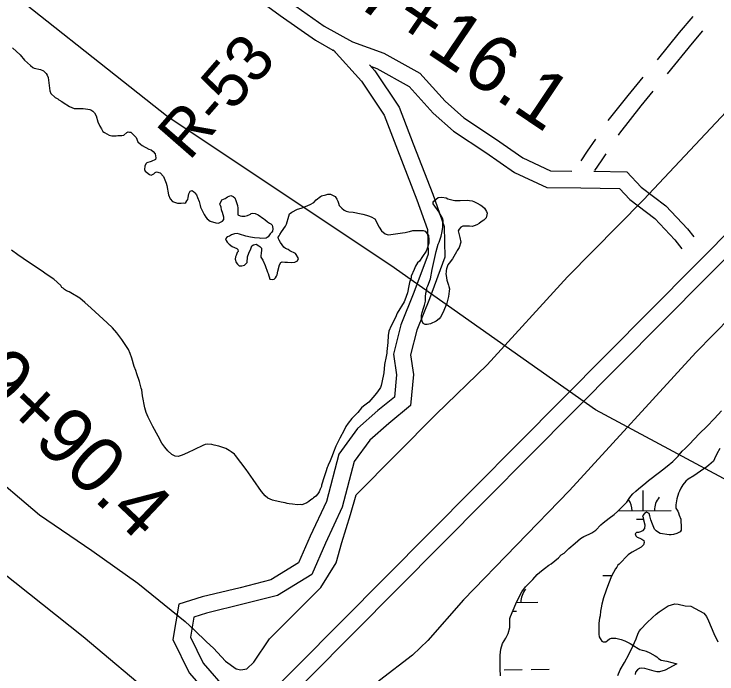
# Model space of a CAD drawing. Extents: x 3146026 to 3183936, y 897894 to 923344.
# Drawn here: x 3174210 to 3175467, y 911149 to 912329 of the extents above; entities that cross this region are included whole.
import ezdxf

# ---------------------------------------------------------------- set-up
doc = ezdxf.new("R2010")
doc.units = 0
for name, color, linetype in [('V-LEVE-TOET', 7, 'Continuous'), ('V-RIVR-RANG-IDEN', 7, 'Continuous'), ('V-ROAD-CNTR', 7, 'Continuous'), ('V-SITE-VEGE', 7, 'Continuous'), ('V-SURV-IDEN', 7, 'Continuous'), ('V-SURV-LINE', 7, 'Continuous'), ('V-TOPO-BNDY', 7, 'Continuous'), ('V-WETL-SWMP', 7, 'Continuous')]:
    doc.layers.add(name, color=color, linetype=linetype)

msp = doc.modelspace()

# ---------------------------------------------------------------- linework, layer by layer
at = {"layer": 'V-LEVE-TOET'}
for points in [[(3172100.1, 913448.3), (3172370.8, 913233.9), (3172398.7, 913212.6), (3172497.8, 913129.1), (3172624.4, 912974.6), (3172787.3, 912807.3), (3172980.7, 912627.4), (3173171.4, 912446.8), (3173377.7, 912260.1), (3173591.1, 912050.9), (3173767.1, 911895.3), (3173843.3, 911824.3), (3173892.6, 911768.4), (3173997.2, 911662.3), (3174154.9, 911518.6), (3174255.5, 911433.9), (3174348.6, 911370.2), (3174431.4, 911311.7), (3174516, 911243.3)], [(3176559, 912918.7), (3176436.3, 912775.6), (3176341.7, 912684.2), (3176241.8, 912571), (3176075.2, 912402.9), (3175880.3, 912204.7), (3175650.4, 911949.6), (3175429.3, 911724.1), (3175203.1, 911477.4), (3175013.4, 911281.9), (3174949.6, 911208.9), (3174922.4, 911183.2), (3174863.1, 911137.7), (3174821.7, 911101.7)], [(3174516, 911243.3), (3174532.2, 911227.5), (3174553.9, 911206.8), (3174566.6, 911195.5), (3174587.9, 911172.2), (3174607, 911158.4), (3174615.1, 911156.6), (3174626.2, 911158.8), (3174638.6, 911170.2), (3174666.6, 911212.4), (3174758.5, 911304.2), (3174785.9, 911348.2), (3174796, 911384.2), (3174811.4, 911434.2), (3174821.7, 911469.5), (3174964.9, 911614.1), (3175056, 911701.9), (3175199.6, 911859.6), (3175335.6, 911997.2), (3175501.9, 912173.9)], [(3174465.1, 911105.1), (3174333.2, 911215.8), (3174187.8, 911331.4)]]:
    msp.add_lwpolyline(points, dxfattribs=at)
at = {"layer": 'V-ROAD-CNTR'}
msp.add_line((3174779.5, 912264.5), (3174779.9, 912264.2), dxfattribs=at)
for points in [[(3174155.7, 912709.2), (3174233.7, 912670.7), (3174298.8, 912628.9), (3174369.4, 912570.8), (3174446, 912498.5), (3174540.9, 912435.8), (3174615.5, 912378.5), (3174685.8, 912326.4), (3174748.6, 912282.2), (3174784.2, 912262.3)], [(3174580.7, 912443.1), (3174633.6, 912402.5), (3174703.3, 912350.7), (3174764.6, 912307.7), (3174815.1, 912279.3), (3174870.9, 912259.2), (3174935.4, 912223.3), (3174980.6, 912173.5), (3175014.1, 912143.9), (3175070.5, 912106.2), (3175119.7, 912072.1), (3175169.2, 912048.9), (3175207.4, 912048.5)], [(3175423.4, 912324.7), (3175399.3, 912296.1), (3175359.9, 912247.5)], [(3175441.2, 912299.4), (3175422.4, 912277), (3175377.8, 912222)], [(3174780.3, 912265.3), (3174831.4, 912209.2), (3174871.4, 912148.6), (3174895.8, 912086.5), (3174930.3, 911996.8), (3174949.2, 911943.8), (3174950.2, 911899.7), (3174924.6, 911831.2), (3174901.2, 911773.6), (3174888.1, 911721.1), (3174894, 911683.9), (3174889.9, 911644.5), (3174860.5, 911620.1), (3174823.8, 911588), (3174790.7, 911542.6), (3174768.5, 911457.7), (3174739.2, 911395.6), (3174718.5, 911348), (3174669, 911317.8), (3174614.2, 911303.6), (3174546, 911287), (3174504.7, 911274.3), (3174493.8, 911210.8), (3174522.8, 911151.6), (3174569.5, 911098.1)], [(3174845.5, 912238.3), (3174855.2, 912227.7), (3174898.2, 912162.5), (3174923.7, 912097.3), (3174958.5, 912007.3), (3174979.1, 911949.3), (3174980.3, 911894.6), (3174952.6, 911820.3), (3174929.8, 911764.3), (3174918.7, 911719.7), (3174924.2, 911684.8), (3174918.5, 911629.3), (3174880, 911597.2), (3174846, 911567.6), (3174818.3, 911529.5), (3174796.8, 911447.5), (3174766.5, 911383.2), (3174742.3, 911327.3), (3174680.8, 911289.9), (3174621.5, 911274.5), (3174554, 911258), (3174531.1, 911251), (3174525, 911215.3), (3174548, 911168.4), (3174591.3, 911118.8)], [(3174849.2, 912235.1), (3174858.5, 912231.8), (3174916.5, 912199.5), (3174959.5, 912152.1), (3174995.8, 912120), (3175053.6, 912081.4), (3175104.7, 912046), (3175162.4, 912018.9), (3175223.6, 912018.4), (3175292.6, 912017.3), (3175310.9, 911997.5), (3175355.5, 911963.6), (3175391.6, 911925.7), (3175404.3, 911909.3)], [(3175334.5, 912216.6), (3175307.3, 912183.8), (3175271.9, 912138.7)], [(3175352.4, 912191.2), (3175330.7, 912164.9), (3175292.6, 912116.5), (3175290.3, 912112.8)], [(3175249.8, 912105.4), (3175235, 912083.8), (3175223.1, 912066.9)], [(3175268.3, 912079.4), (3175259.6, 912066.7), (3175247.6, 912049.7)], [(3175246.4, 912048), (3175305.9, 912047.1), (3175331.2, 912019.8), (3175375.5, 911986), (3175414.4, 911945.3), (3175425.5, 911930.9)]]:
    msp.add_lwpolyline(points, dxfattribs=at)
at = {"layer": 'V-SITE-VEGE'}
for points in [[(3174206.8, 912268.9), (3174220.9, 912256), (3174228.7, 912246.6), (3174238.9, 912236.9), (3174243.2, 912233.4), (3174245.9, 912232.2), (3174257.3, 912229.9), (3174262.4, 912227.5), (3174267, 912222.9), (3174269, 912220.1), (3174271, 912215.5), (3174273.7, 912192), (3174275.3, 912186.9), (3174283.5, 912179.9), (3174288.2, 912177.6), (3174289.8, 912176), (3174294.9, 912172.9), (3174297.6, 912171), (3174309, 912163.9), (3174317.2, 912160.1), (3174333.6, 912160.1), (3174341.4, 912159.3), (3174345.3, 912158.5), (3174347.2, 912157.8), (3174350.8, 912155.8), (3174353.9, 912152.7), (3174356.6, 912147.2), (3174359.8, 912136.7), (3174362.9, 912128.9), (3174366.1, 912124.2), (3174368.8, 912119.1), (3174371.5, 912117.2), (3174379.8, 912112.5), (3174384.4, 912111.3), (3174386.8, 912111.7), (3174392.6, 912111.7), (3174395.4, 912112.1), (3174402.4, 912112.1), (3174405.9, 912112.9), (3174411.4, 912117.2), (3174413.7, 912118.4), (3174416.1, 912118), (3174418.8, 912118), (3174428.2, 912108.7), (3174431, 912100.9), (3174435.6, 912096.6), (3174438.8, 912094.2), (3174450.9, 912087.6), (3174454.8, 912086.5), (3174458.7, 912083.3), (3174461.9, 912079.4), (3174463.4, 912072), (3174462.7, 912069.3), (3174454.8, 912065.4), (3174447.4, 912063), (3174445.5, 912061.4), (3174443.5, 912057.1), (3174442.8, 912051.3), (3174444.3, 912048.5), (3174446.7, 912046.2), (3174451.8, 912042.3), (3174454.9, 912041.1), (3174459.6, 912043.5), (3174462.3, 912045.8)], [(3174462.3, 912045.8), (3174464.6, 912047), (3174470.9, 912045.1), (3174476.8, 912038.8), (3174479.5, 912032.6), (3174481.9, 912026.7), (3174483, 912022.8), (3174485.8, 912006), (3174489, 911998.6), (3174493.3, 911994.3), (3174502.2, 911991.2), (3174505.4, 911991.2), (3174508.5, 911990.8), (3174512.4, 911991.6), (3174515.1, 911991.2), (3174517.1, 911992.4), (3174519, 911995.1), (3174520.6, 911997.9), (3174521.4, 912001), (3174522.5, 912008), (3174524.9, 912012.7), (3174528, 912013.5), (3174531.1, 912011.6), (3174533.1, 912009.6), (3174535.8, 912006.1), (3174537.8, 912001), (3174540.9, 911994), (3174542.5, 911987), (3174543.3, 911984.2), (3174546, 911978), (3174548.8, 911972.9), (3174549.6, 911971), (3174552.7, 911965.9), (3174555.4, 911963.2), (3174560.5, 911958.9), (3174570.7, 911955.8), (3174575.4, 911955.4), (3174580, 911957.4), (3174582.4, 911958.9), (3174585.1, 911961.7), (3174585.1, 911966), (3174582.4, 911974.2), (3174581.6, 911977.3), (3174580.8, 911979.2), (3174580, 911983.9), (3174578.8, 911987), (3174577.7, 911989.4), (3174581.5, 911996.8), (3174587, 911999.6), (3174589, 912000.3), (3174591.3, 912002.3), (3174597.2, 912005), (3174601.5, 912003.1), (3174604.6, 912000.4), (3174606.6, 911995.7), (3174609.3, 911986.7), (3174610.1, 911982.4), (3174610.1, 911977.7), (3174609.7, 911975), (3174610.1, 911970.3), (3174614.4, 911968.4), (3174617.1, 911968), (3174622.6, 911968), (3174627.3, 911969.2), (3174632.4, 911971.1), (3174633.9, 911972.7), (3174636.3, 911973.1), (3174641, 911972.3), (3174646.1, 911970), (3174656.2, 911963), (3174658.2, 911961.8), (3174662.9, 911957.5), (3174666.4, 911955.5), (3174668.7, 911954), (3174671.1, 911951.6), (3174671.9, 911949.3), (3174672.3, 911945.4), (3174671.9, 911941.1), (3174670.7, 911939.1), (3174668, 911936.4), (3174664.1, 911930.9), (3174660.6, 911928.6), (3174651.2, 911927.8), (3174648.9, 911928.6), (3174639.5, 911928.9), (3174632.4, 911930.5), (3174624.2, 911932), (3174612.9, 911935.5), (3174608.6, 911936.7), (3174603.9, 911936.3), (3174598.5, 911934.3), (3174594.9, 911932), (3174591, 911930.8), (3174587.9, 911927.3), (3174589.1, 911924.6), (3174591, 911921.4), (3174594.6, 911917.9), (3174600.1, 911913.6), (3174608.3, 911910.1), (3174609.8, 911908.2), (3174610.6, 911904.7)], [(3174610.6, 911904.7), (3174608.7, 911902.7), (3174607.1, 911897.6), (3174605.9, 911894.9), (3174605.2, 911891), (3174606.7, 911884.7), (3174609.1, 911882), (3174612.2, 911879.3), (3174615, 911878.9), (3174617.3, 911878.9), (3174622, 911880.1), (3174626.7, 911884.8), (3174627.4, 911895.3), (3174629.4, 911901.6), (3174633.3, 911909.4), (3174635.2, 911914.9), (3174637.9, 911916.4), (3174642.6, 911918), (3174647.3, 911914.9), (3174649.3, 911913.3), (3174652, 911910.6), (3174652.4, 911907.5), (3174651.6, 911900.8), (3174650.9, 911897.3), (3174650.9, 911894.6), (3174654.4, 911889.1), (3174659.1, 911879.4), (3174663, 911868), (3174664.2, 911865.3), (3174667.3, 911855.1), (3174671.3, 911854.4), (3174674.8, 911855.2), (3174677.1, 911857.5), (3174679.1, 911860.6), (3174680.2, 911863), (3174681.4, 911869.6), (3174684.5, 911881), (3174686.8, 911884.9), (3174689.2, 911886), (3174693.9, 911885.7), (3174698.5, 911885.7), (3174706.8, 911884.9), (3174711.8, 911885.7), (3174716.5, 911888), (3174718.5, 911892.3), (3174714.5, 911899.4), (3174713, 911900.9), (3174703.2, 911906), (3174700.1, 911908.3), (3174695, 911910.3), (3174692.3, 911912.2), (3174689.1, 911916.5), (3174686.4, 911920.8), (3174683.6, 911924.7), (3174682.5, 911927.1), (3174682.1, 911930.2), (3174684, 911932.9), (3174685.2, 911935.3), (3174688.3, 911940), (3174695.3, 911949.7), (3174696.9, 911953.6), (3174701.1, 911967.7), (3174702.3, 911972), (3174706.6, 911975.2), (3174716.7, 911980.2), (3174723.4, 911982.2), (3174730.8, 911985), (3174739.4, 911988.5), (3174746, 911992.4), (3174750.3, 911997.1), (3174757.7, 912003), (3174759.7, 912004.2), (3174767.5, 912006.1), (3174771, 912007.3), (3174775.7, 912006.9), (3174783.9, 912003), (3174787, 911998.3), (3174789, 911994.8), (3174789.8, 911991.3), (3174791.4, 911987), (3174796.1, 911981.9), (3174800, 911978.8), (3174803.9, 911976.5), (3174808.2, 911975.7), (3174816, 911974.9), (3174830.8, 911971.9), (3174833.6, 911971.1), (3174840.2, 911969.9), (3174843.4, 911968.4), (3174848.4, 911966.4), (3174855.1, 911963.3), (3174857.4, 911959), (3174860.2, 911952.4), (3174862.5, 911948.1), (3174866.8, 911941.8), (3174873.5, 911936), (3174877, 911934.8), (3174879.4, 911934.4), (3174892.2, 911936.4), (3174904.7, 911938), (3174909.4, 911938.8)], [(3174909.4, 911938.8), (3174913.7, 911940), (3174917.2, 911940.4), (3174923.1, 911941.9), (3174926.2, 911941.9), (3174934.8, 911942.3), (3174941.5, 911942.3), (3174945, 911941.2), (3174950.8, 911933), (3174951.6, 911926), (3174951.6, 911923.2), (3174951.3, 911919.3), (3174948.5, 911909.9), (3174946.6, 911905.2), (3174940.4, 911895.5), (3174934.9, 911887.3), (3174931, 911884.1), (3174927.5, 911878.6), (3174925.2, 911872.4), (3174920.1, 911860.3), (3174919.7, 911857.5), (3174917, 911849.3), (3174915.5, 911843.5), (3174913.1, 911831), (3174908.9, 911817.7), (3174907.7, 911814.5), (3174894.8, 911794.2), (3174891.7, 911786.8), (3174883.9, 911771.5), (3174880, 911762.5), (3174878.9, 911754.7), (3174878.1, 911741.8), (3174876.6, 911725.8), (3174876.6, 911722.7), (3174875, 911716.8), (3174872.3, 911702.4), (3174870.8, 911687.5), (3174867.7, 911670.7), (3174866.5, 911664.8), (3174865, 911661.3), (3174859.9, 911653.9), (3174854.8, 911647.6), (3174844.3, 911635.5), (3174834.6, 911628.1), (3174831.1, 911624.9), (3174824.4, 911617.1), (3174821.7, 911613.6), (3174817, 911608.9), (3174813.9, 911606.1), (3174807.3, 911597.9), (3174803, 911591.7), (3174799.9, 911585), (3174792.1, 911570.9), (3174785.1, 911556.9), (3174781.2, 911545.9), (3174778.5, 911539.3), (3174775.3, 911530.7), (3174771.5, 911522.9), (3174770.7, 911520.9), (3174769.9, 911518.6), (3174767.2, 911510.7), (3174764.1, 911501.7), (3174759.8, 911486.9), (3174759.4, 911484.5), (3174757.8, 911481), (3174757.1, 911479.5), (3174755.5, 911475.2), (3174753.2, 911471.3), (3174749.7, 911467), (3174745.4, 911464.2), (3174743.4, 911462.3), (3174740.7, 911460.7), (3174736.8, 911457.9), (3174733.3, 911455.6), (3174729, 911453.6), (3174724.3, 911451.7), (3174721.6, 911452.1), (3174716.9, 911452), (3174707.5, 911452.8), (3174701.6, 911453.6), (3174698.1, 911454.4), (3174694.6, 911455.1), (3174687.2, 911456.3), (3174674.3, 911459.4), (3174671.9, 911459.8), (3174663.7, 911463.7), (3174658.6, 911468), (3174652, 911475.4), (3174637.1, 911496.8), (3174633.2, 911503.1), (3174628.9, 911508.9), (3174625, 911514.8), (3174615.2, 911527.7), (3174605.8, 911540.2), (3174603.8, 911542.1), (3174598.3, 911546.4), (3174594.4, 911548.7), (3174588.2, 911552.6), (3174575.7, 911556.9), (3174567.5, 911558.4), (3174563.5, 911559.6)], [(3174563.5, 911559.6), (3174555.7, 911560.4), (3174551.4, 911559.6), (3174547.5, 911557.6), (3174532.3, 911550.6), (3174520.2, 911544.7), (3174510.1, 911540.8), (3174503.4, 911538.4), (3174497.6, 911538.8), (3174491.7, 911541.9), (3174484.6, 911548.5), (3174479.6, 911554.8), (3174474.1, 911561.8), (3174467.4, 911574.3), (3174458, 911591.5), (3174449.4, 911608.6), (3174445.9, 911616.8), (3174443.5, 911625.4), (3174439.5, 911646.9), (3174438, 911657.1), (3174436.8, 911660.6), (3174434, 911672.3), (3174429.3, 911686), (3174427.4, 911692.2), (3174424.6, 911699.2), (3174420.3, 911713.7), (3174417.5, 911722.3), (3174414.4, 911729.3), (3174402.7, 911747.3), (3174393.6, 911759.3), (3174385.8, 911767.9), (3174376, 911776.9), (3174347.9, 911803.4), (3174336.5, 911813.2), (3174327.1, 911821), (3174311.1, 911830.7), (3174308.3, 911832.3), (3174303.3, 911834.6), (3174299.7, 911836.9), (3174297.4, 911838.9), (3174295.4, 911840.1), (3174293.1, 911844), (3174280.6, 911854.9), (3174269.2, 911862.7), (3174258.3, 911870.5), (3174235.6, 911885.3), (3174216.4, 911898.9), (3174205.1, 911907.1)], [(3175289.3, 911146.6), (3175293.5, 911156.8), (3175301.3, 911170.1), (3175309.1, 911184.2), (3175316.5, 911199), (3175322.3, 911212.3), (3175325.8, 911222.1), (3175328.2, 911226.4), (3175330.5, 911229.5), (3175341.4, 911240.9), (3175351.6, 911250.3), (3175358.2, 911256.1), (3175363.7, 911260.4), (3175369.1, 911264.3), (3175379.7, 911271.4), (3175391.8, 911274.5), (3175397.6, 911274.2), (3175410.1, 911271.4), (3175420.3, 911270.3), (3175443.4, 911258.2), (3175448.1, 911252), (3175452, 911244.2), (3175461, 911221.9), (3175468.5, 911206.7)]]:
    msp.add_lwpolyline(points, dxfattribs=at)
msp.add_lwpolyline([(3174954.7, 911855.9), (3174957.3, 911872.4), (3174960, 911883.2), (3174962.3, 911894.1), (3174963.2, 911899.1), (3174964.6, 911904.7), (3174968.4, 911917.6), (3174970.2, 911921.5), (3174973.7, 911932.1), (3174975.5, 911940.3), (3174976.3, 911947.9), (3174976.6, 911953.5), (3174977.2, 911960), (3174976.3, 911962.9), (3174974.5, 911966.5), (3174970.7, 911972.9), (3174969.8, 911975), (3174959.5, 911990), (3174959.5, 911992.6), (3174960.4, 911994.7), (3174968, 912001.1), (3174974.8, 912001.7), (3174982.4, 912000.3), (3174985.3, 911999.1), (3174995.3, 911996.2), (3174998.3, 911995.6), (3175005.1, 911995.6), (3175007.7, 911995.9), (3175020.6, 911996.2), (3175024.5, 911995.9), (3175029.2, 911995.1), (3175032.1, 911994.2), (3175035.6, 911992.4), (3175037.7, 911991), (3175043.3, 911988), (3175046.2, 911986), (3175051.2, 911981.9), (3175054.8, 911976.3), (3175055.7, 911973.1), (3175055.4, 911970.4), (3175053.9, 911964.8), (3175050.1, 911960.7), (3175045.1, 911957.5), (3175041.6, 911954.8), (3175037.2, 911952.5), (3175032.8, 911950.4), (3175029.2, 911949.5), (3175024.2, 911949.8), (3175012.2, 911949.8), (3175009, 911948.3), (3175005.7, 911944.8), (3175004.3, 911941.5), (3175004.6, 911939.5), (3175007.2, 911929.8), (3175009, 911921.5), (3175005.8, 911911.8), (3175002.3, 911906.2), (3175000.8, 911904.2), (3174994.1, 911891.8), (3174987.9, 911883.9), (3174985.8, 911880.9), (3174982.9, 911873.6), (3174982.3, 911870.9), (3174982.3, 911868.3), (3174982.1, 911864.8), (3174982.4, 911861.8), (3174983.8, 911853.3), (3174986.8, 911844.2), (3174987.1, 911842.1), (3174988.3, 911837.7), (3174988, 911833.6), (3174986.8, 911824.2), (3174983.6, 911812.4), (3174976.9, 911796), (3174972.5, 911787.4), (3174970.1, 911784.5), (3174964.6, 911780.1), (3174954.3, 911775.3), (3174948.7, 911774.2), (3174944.9, 911774.1), (3174941.6, 911776.2), (3174939.6, 911780), (3174938.7, 911785.9), (3174938.7, 911790.6), (3174939.5, 911795.6), (3174941.9, 911803.5), (3174943.6, 911808.8), (3174945.4, 911815.9), (3174945.7, 911823.5), (3174946.2, 911830.3), (3174947.7, 911836.5), (3174948, 911839.4), (3174949.8, 911843.2)], close=True, dxfattribs=at)
at = {"layer": 'V-SURV-LINE'}
for points in [[(3174636.9, 911083.7), (3175506.8, 911959.7)], [(3175528.1, 911938.5), (3174658.2, 911062.6)]]:
    msp.add_lwpolyline(points, dxfattribs=at)
at = {"layer": 'V-TOPO-BNDY'}
msp.add_lwpolyline([(3176856.6, 910386.2), (3176814.3, 910437.3), (3176728.4, 910587.3), (3176643.2, 910736.9), (3176419.3, 910929.6), (3176094.5, 911180.9), (3175633.9, 911415.2), (3175249.7, 911621.4), (3174883.6, 911879.4), (3174485.2, 912144.9), (3174133.9, 912423.2), (3173763.7, 912766.5), (3173388.4, 913116.7), (3173045.4, 913402.9), (3172482.4, 913854.3), (3172147.4, 914130.1)], dxfattribs=at)
at = {"layer": 'V-WETL-SWMP'}
for p, q in [((3175335, 911441.4), (3175334.7, 911477.4)), ((3175290.2, 911441), (3175385, 911441.9)), ((3175323.2, 911425.9), (3175335.2, 911426)), ((3175262.8, 911325.3), (3175278.9, 911325.5)), ((3175108.4, 911277.3), (3175146.2, 911277.7)), ((3175101.6, 911261.8), (3175108.3, 911261.9)), ((3175086.5, 911157), (3175118.5, 911157.3)), ((3175134.5, 911157.5), (3175166.5, 911157.8))]:
    msp.add_line(p, q, dxfattribs=at)
for points in [[(3175080, 911145.8), (3175079.1, 911158.3), (3175079.2, 911162.9), (3175079, 911177.1), (3175079.4, 911182.9), (3175080.5, 911193.6), (3175083.4, 911204), (3175089.2, 911213.1), (3175091.9, 911218), (3175093.3, 911221.8), (3175096.2, 911232.4), (3175096.6, 911236.2), (3175096.6, 911248.6), (3175097.5, 911252.2), (3175107.2, 911274.8), (3175113.6, 911288.3), (3175117.8, 911296.3), (3175124.5, 911305.2), (3175131.9, 911312.9), (3175137.7, 911318.1), (3175145.5, 911326.9), (3175150.1, 911331.4), (3175158.3, 911338.2), (3175166.4, 911343.7), (3175170.3, 911346.4), (3175183.7, 911357), (3175188.4, 911362.1), (3175193.7, 911365.4), (3175199.1, 911370.6), (3175202, 911373.7), (3175213.1, 911383.4), (3175222.7, 911391.4), (3175228.6, 911395.2), (3175238, 911399.5), (3175242.9, 911401.5), (3175250, 911406.6), (3175258.9, 911415.9), (3175263.1, 911419.7), (3175274, 911427.7), (3175282.9, 911434.6), (3175289.1, 911439.9), (3175293.6, 911444.3), (3175299.6, 911450.3), (3175305.6, 911456.7), (3175309.9, 911463.2), (3175313, 911467.4), (3175316.5, 911471.3), (3175321.7, 911476), (3175326.8, 911480.2), (3175339.4, 911491.1), (3175344.3, 911495.1), (3175364.1, 911510.1), (3175369.2, 911514.3), (3175377.9, 911520.9), (3175388.2, 911529.4), (3175393.9, 911535.1), (3175397.3, 911538.7), (3175399.3, 911541.4), (3175404.8, 911547.6), (3175410.2, 911552.6), (3175418, 911560), (3175426, 911569), (3175435.6, 911579), (3175448.7, 911591.6), (3175462.3, 911606), (3175474.9, 911620)], [(3175471.9, 911552.3), (3175466.8, 911542.8), (3175462.6, 911533.8), (3175460.6, 911529.6), (3175452.3, 911522.8), (3175448.9, 911519.8), (3175446.1, 911517.9), (3175443.6, 911516), (3175425.4, 911503.8), (3175415.6, 911497.9), (3175411.4, 911494.1), (3175405.8, 911487.7), (3175402, 911481.5), (3175399.6, 911476.4), (3175398.1, 911472.6), (3175394.9, 911462.6), (3175393.6, 911455.3), (3175393.2, 911451.7), (3175393.2, 911445.8), (3175396.6, 911440.4), (3175398.2, 911437.2), (3175399.3, 911433.4), (3175402.1, 911425.9), (3175403.1, 911409.8), (3175402.9, 911406.6), (3175401, 911403.6), (3175395.2, 911400.2), (3175389, 911398.5), (3175385.2, 911398.1), (3175381.6, 911398.1), (3175365, 911400.7), (3175360.7, 911403.2), (3175357.9, 911405.2), (3175355.4, 911408.1), (3175351.4, 911417.3), (3175348.4, 911425.2), (3175346.9, 911432), (3175345.4, 911436.1), (3175340.7, 911438.4), (3175337.1, 911436.5), (3175333.9, 911432.3), (3175334.6, 911429.3), (3175335.4, 911424.8), (3175338.1, 911416.1), (3175337.5, 911409.7), (3175333.7, 911405.4), (3175330, 911403.5), (3175326.4, 911402.5), (3175322.8, 911402.5), (3175320.7, 911399.9), (3175321.5, 911396.5), (3175324.3, 911393.9), (3175329.1, 911392), (3175332.3, 911390.3), (3175335.8, 911387.9), (3175336.8, 911384.5), (3175335.3, 911380.5), (3175331.3, 911376.3), (3175315.3, 911367.3), (3175312.5, 911365.4), (3175308.2, 911362.2), (3175291.8, 911345.9), (3175289.7, 911343.7), (3175287.7, 911340.5), (3175285.2, 911337.1), (3175278.1, 911324), (3175272.6, 911310.6), (3175268.7, 911299.3), (3175264.2, 911285.2)], [(3175264.2, 911285.2), (3175261, 911273.9), (3175259.5, 911267.5), (3175258.6, 911261.4), (3175257.7, 911253.3), (3175256.7, 911249.4), (3175255.4, 911240.1), (3175255.3, 911228.6), (3175255.6, 911220.5), (3175256, 911216), (3175257.9, 911212.6), (3175260.9, 911208.1), (3175263.6, 911206.6), (3175268.1, 911206.8), (3175271.3, 911209.4), (3175274.5, 911212.4), (3175278.1, 911213.6), (3175285.8, 911213.2), (3175295.4, 911210.8), (3175302.2, 911208.7), (3175311.7, 911204), (3175317.9, 911199.5), (3175326, 911194.6), (3175329.2, 911193.1), (3175332.8, 911192), (3175336, 911191.4), (3175340.5, 911190.1), (3175346.6, 911187.3), (3175356.4, 911182), (3175359.2, 911180.2), (3175362.4, 911177.2), (3175367.3, 911174.3), (3175376.9, 911172.3), (3175395.2, 911167.4), (3175374.3, 911156.1), (3175363.8, 911153.2), (3175359.6, 911153.3), (3175354.5, 911154.4), (3175337.9, 911158.9), (3175332.7, 911159.8), (3175328.1, 911159.1), (3175324.8, 911156.7), (3175321, 911152.5), (3175320.5, 911148.5)]]:
    msp.add_lwpolyline(points, dxfattribs=at)
for centre, start, end in [((3175279.8, 911441.4), 359.7992, 34.7052), ((3175390.3, 911442.5), 139.7992, 181.3429), ((3175151.4, 911278.2), 139.7992, 181.3429)]:
    msp.add_arc(centre, 35.2, start, end, dxfattribs=at)

# ---------------------------------------------------------------- texts
at = {"layer": 'V-RIVR-RANG-IDEN'}
msp.add_text('R-53', height=83, rotation=48.9072, dxfattribs=at).set_placement((3174522.9, 912065.3))
at = {"layer": 'V-SURV-IDEN'}
for s, rotation, p in [('827+16.1', 326.1061, (3174694.2, 912429.7)), ('839+90.4', 316.5961, (3174023.3, 911770.7))]:
    msp.add_text(s, height=100, rotation=rotation, dxfattribs=at).set_placement(p)

doc.saveas('drawing.dxf')
